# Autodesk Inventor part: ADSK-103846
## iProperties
Shininess: 20.0
Created: 2001-05
Part Number: ADSK-103846
Document SubType Name: Modeling
Designer: Administrator
Stock Number: ADSK-103846
Density: 1 g/cm^3
Density: 0.0
Volumn: 0.0
Area: 0.0
PropertySet Name: Model Information
Control State: 0
Master: False
Checked Out: False
Author: Administrator
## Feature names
1. Extrusion1
2. Extrusion2
3. Hole1
4. Circular Pattern1
5. Chamfer1
6. Extrusion3
